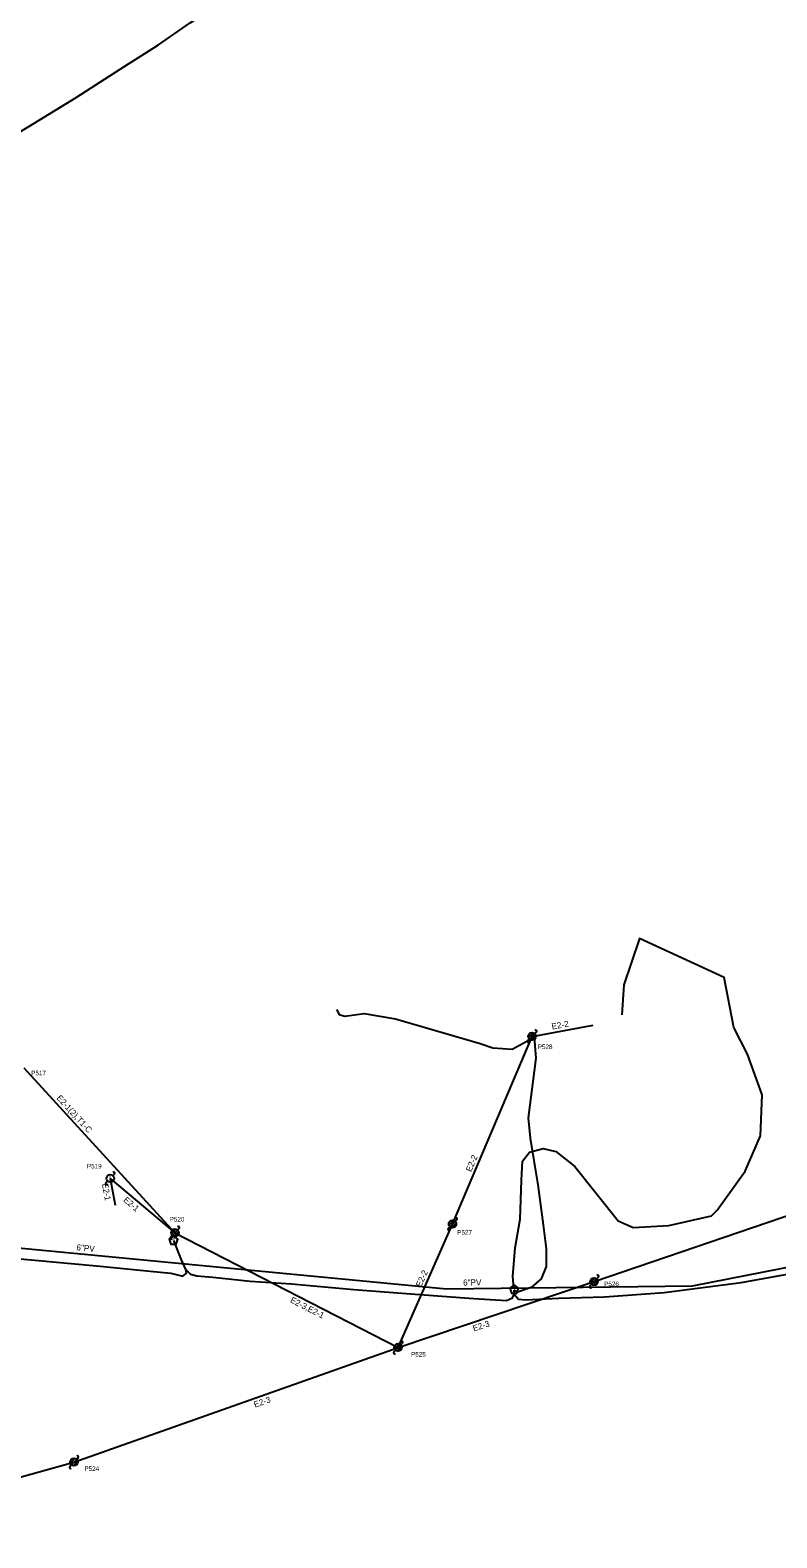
# Model space of a CAD drawing. Extents: x 1741604 to 1825760, y 1164229 to 1194908.
# Drawn here: x 1813275 to 1813765, y 1190349 to 1191338 of the extents above; entities that cross this region are included whole.
import ezdxf

# ---------------------------------------------------------------- set-up
doc = ezdxf.new("R2010")
doc.units = 0
for name, color, linetype in [('RD_EX_SU_Elec', 7, 'Continuous'), ('RD_EX_SU_H2O', 7, 'Continuous'), ('RD_EX_SU_Ovhd', 7, 'Continuous'), ('RD_EX_SU_Pole', 7, 'Continuous'), ('RD_EX_SU_Telecom', 7, 'Continuous'), ('RD_EX_SU_TX_H2O', 7, 'Continuous'), ('RD_EX_SU_TX_Pole', 7, 'Continuous')]:
    doc.layers.add(name, color=color, linetype=linetype)

# ---------------------------------------------------------------- blocks, each defined once
blk = doc.blocks.new('SUE_TPP')
at = {"layer": 'RD_EX_SU_Telecom'}
blk.add_lwpolyline([(0, 3), (-2.85, 0.93), (-1.76, -2.43), (1.76, -2.43), (2.85, 0.93)], close=True, dxfattribs=at)
blk.add_text('T', height=3.75, dxfattribs=at).set_placement((-1.25, -1.88))

msp = doc.modelspace()

# ---------------------------------------------------------------- linework, layer by layer
at = {"layer": 'RD_EX_SU_Elec'}
msp.add_lwpolyline([(1813074.17, 1191147.22), (1813079.49, 1191142.73), (1813083.35, 1191146.53), (1813090.24, 1191152.3), (1813113.65, 1191170.54), (1813131.4, 1191183.04), (1813147.43, 1191193.7), (1813174.94, 1191210.3), (1813193.18, 1191222.5), (1813212.55, 1191236.51), (1813242.91, 1191256.26), (1813274.11, 1191274.83), (1813305.14, 1191293.76), (1813336.93, 1191314.29), (1813359.03, 1191328.39), (1813379.8, 1191342.76), (1813412.74, 1191364.15), (1813434.94, 1191378.63), (1813468.04, 1191399.22), (1813497.48, 1191419.37)], dxfattribs=at)
at = {"layer": 'RD_EX_SU_H2O'}
msp.add_lwpolyline([(1813137.28, 1190560.13), (1813168.69, 1190548.44), (1813548.05, 1190512.01), (1813709.49, 1190513.95), (1813790.71, 1190529.92), (1813879.02, 1190555.32), (1814045.36, 1190620.16), (1814170.98, 1190673.34), (1814340.25, 1190745.39), (1814593.33, 1190851.84), (1815112.4, 1191071.44), (1815429.86, 1191203.06), (1815618.35, 1191283.39), (1815883.49, 1191395.05), (1816374.39, 1191600.1)], dxfattribs=at)
at = {"layer": 'RD_EX_SU_Ovhd'}
for p, q in [((1813604.22, 1190677.72), (1813644.26, 1190684.95)), ((1813552.01, 1190554.53), (1813604.22, 1190677.72)), ((1813270.85, 1190657.03), (1813369.89, 1190548.84)), ((1813644.92, 1190516.83), (1813856.8, 1190589.16)), ((1813327.48, 1190584.47), (1813369.89, 1190548.84)), ((1813327.48, 1190584.47), (1813330.66, 1190566.99)), ((1813369.89, 1190548.84), (1813516.3, 1190473.57)), ((1813516.3, 1190473.57), (1813552.01, 1190554.53)), ((1813516.3, 1190473.57), (1813644.92, 1190516.83)), ((1813303.67, 1190398.31), (1813516.3, 1190473.57)), ((1813113.89, 1190345.79), (1813303.67, 1190398.31))]:
    msp.add_line(p, q, dxfattribs=at)
at = {"layer": 'RD_EX_SU_Pole'}
for p, q in [((1813601.39, 1190674.89), (1813602.46, 1190675.95)), ((1813601.81, 1190677.07), (1813604.87, 1190680.13)), ((1813602.46, 1190675.95), (1813605.99, 1190679.49)), ((1813603.58, 1190675.3), (1813606.64, 1190678.36)), ((1813605.99, 1190679.49), (1813607.05, 1190680.55)), ((1813329.25, 1190586.23), (1813330.31, 1190587.29)), ((1813324.65, 1190581.64), (1813325.72, 1190582.7)), ((1813549.59, 1190553.89), (1813552.65, 1190556.95)), ((1813550.24, 1190552.76), (1813553.77, 1190556.3)), ((1813553.77, 1190556.3), (1813554.84, 1190557.36)), ((1813367.06, 1190546.01), (1813368.13, 1190547.07)), ((1813367.48, 1190548.19), (1813370.54, 1190551.25)), ((1813368.13, 1190547.07), (1813371.66, 1190550.61)), ((1813369.25, 1190546.42), (1813372.31, 1190549.49)), ((1813371.66, 1190550.61), (1813372.72, 1190551.67)), ((1813549.18, 1190551.7), (1813550.24, 1190552.76)), ((1813551.36, 1190552.12), (1813554.42, 1190555.18)), ((1813642.5, 1190516.19), (1813645.56, 1190519.25)), ((1813643.15, 1190515.07), (1813646.68, 1190518.6)), ((1813644.27, 1190514.42), (1813647.33, 1190517.48)), ((1813646.68, 1190518.6), (1813647.74, 1190519.66)), ((1813642.09, 1190514.01), (1813643.15, 1190515.07)), ((1813513.47, 1190470.74), (1813514.53, 1190471.8)), ((1813513.89, 1190472.92), (1813516.95, 1190475.99)), ((1813514.53, 1190471.8), (1813518.07, 1190475.34)), ((1813515.65, 1190471.16), (1813518.72, 1190474.22)), ((1813518.07, 1190475.34), (1813519.13, 1190476.4)), ((1813301.26, 1190397.67), (1813304.32, 1190400.73)), ((1813301.91, 1190396.54), (1813305.44, 1190400.08)), ((1813303.03, 1190395.9), (1813306.09, 1190398.96)), ((1813305.44, 1190400.08), (1813306.5, 1190401.14)), ((1813300.85, 1190395.48), (1813301.91, 1190396.54))]:
    msp.add_line(p, q, dxfattribs=at)
for centre in [(1813604.22, 1190677.72), (1813327.48, 1190584.47), (1813552.01, 1190554.53), (1813369.89, 1190548.84), (1813644.92, 1190516.83), (1813516.3, 1190473.57), (1813303.67, 1190398.31)]:
    msp.add_circle(centre, 2.5, dxfattribs=at)
for centre, start, end in [((1813601.92, 1190674.36), 135, 315), ((1813606.52, 1190681.08), 315, 135), ((1813329.78, 1190587.82), 315, 135), ((1813325.19, 1190581.11), 135, 315), ((1813554.3, 1190557.89), 315, 135), ((1813372.19, 1190552.2), 315, 135), ((1813549.71, 1190551.17), 135, 315), ((1813367.6, 1190545.48), 135, 315), ((1813647.21, 1190520.19), 315, 135), ((1813642.62, 1190513.48), 135, 315), ((1813518.6, 1190476.93), 315, 135), ((1813514, 1190470.21), 135, 315), ((1813305.97, 1190401.67), 315, 135), ((1813301.38, 1190394.95), 135, 315)]:
    msp.add_arc(centre, 0.75, start, end, dxfattribs=at)
at = {"layer": 'RD_EX_SU_Telecom'}
for points in [[(1813592.2, 1190512.27), (1813591.58, 1190520.2), (1813593.18, 1190538.89), (1813596.31, 1190557.84), (1813597.23, 1190583.39), (1813598.01, 1190595.83), (1813602.63, 1190601.72), (1813611.45, 1190604.04), (1813619.86, 1190602.19), (1813632.34, 1190592.39), (1813660.73, 1190556.55), (1813670.43, 1190552.36), (1813694.01, 1190553.55), (1813721.92, 1190559.95), (1813725.59, 1190563.57), (1813744.01, 1190589.22), (1813754.07, 1190612.54), (1813755.22, 1190639.35), (1813745.52, 1190665.97), (1813736.63, 1190683.45), (1813730.24, 1190716.26), (1813674.79, 1190741.98), (1813664.43, 1190711.59), (1813663.14, 1190691.81)], [(1813475.8, 1190695.38), (1813477.62, 1190691.96), (1813481.36, 1190690.96), (1813494, 1190692.66), (1813514.57, 1190689.18), (1813570.15, 1190673.12), (1813578.4, 1190670.16), (1813591.13, 1190669.29), (1813605.49, 1190677.21), (1813606.58, 1190663.31), (1813601.62, 1190624.21), (1813603.06, 1190610.93), (1813608.04, 1190580.18), (1813611.56, 1190554.08), (1813613.49, 1190538.25), (1813613.46, 1190526.59), (1813610.15, 1190518.68), (1813603.69, 1190512.91), (1813594.54, 1190509.9), (1813592.66, 1190511.16)], [(1813592.51, 1190508.63), (1813595.25, 1190505.28), (1813600.31, 1190504.81), (1813621.53, 1190505.89), (1813651.78, 1190506.69), (1813690.9, 1190509.66), (1813741.46, 1190516.19), (1813781.4, 1190523.39), (1813863.95, 1190545.47), (1813866.26, 1190551.47), (1813865.54, 1190556.28), (1813864.71, 1190557.84)], [(1813253.99, 1190533.12), (1813320.8, 1190526.93), (1813353.75, 1190523.6), (1813367.13, 1190522.28), (1813375.09, 1190520.41), (1813377.41, 1190522.28), (1813377.12, 1190524.81), (1813374.11, 1190530.98), (1813369.18, 1190543.74)], [(1813377.12, 1190524.81), (1813380.14, 1190521.61), (1813384.35, 1190520.53), (1813394.68, 1190519.71), (1813419.26, 1190517.09), (1813446.34, 1190515.21), (1813487.32, 1190511.57), (1813527.51, 1190508.49), (1813565.97, 1190505.66), (1813587.53, 1190504.42), (1813591.47, 1190506.03), (1813592.51, 1190508.63), (1813592.56, 1190511.19)]]:
    msp.add_lwpolyline(points, dxfattribs=at)

# ---------------------------------------------------------------- block references
for p in [(1813369.03, 1190543.78), (1813592.42, 1190511.55)]:
    msp.add_blockref('SUE_TPP', p, dxfattribs=at)

# ---------------------------------------------------------------- texts
at = {"layer": 'RD_EX_SU_Ovhd'}
for s, rotation, p in [('E2-2', 10.24048, (1813617.38, 1190682.13)), ('E2-1(2),T1-C', 312.47407, (1813291.9, 1190636.99)), ('E2-2', 67.02877, (1813564.21, 1190588.44)), ('E2-1', 280.29074, (1813322.04, 1190580.83)), ('E2-1', 319.96735, (1813335.7, 1190569.73)), ('E2-2', 66.201, (1813531.42, 1190512.82)), ('E2-3,E2-1', 332.79256, (1813445.17, 1190503.39)), ('E2-3', 18.59164, (1813566.07, 1190483.98)), ('E2-3', 19.49137, (1813422.46, 1190433.99))]:
    msp.add_text(s, height=4, rotation=rotation, dxfattribs=at).set_placement(p)
at = {"layer": 'RD_EX_SU_Pole'}
msp.add_text('L', height=4, dxfattribs=at).set_placement((1813326.62, 1190582.47))
at = {"layer": 'RD_EX_SU_TX_H2O'}
for rotation, p in [(354.51577, (1813305.11, 1190537.35)), (0.68711, (1813558.98, 1190514.14))]:
    msp.add_text('6"PV', height=4, rotation=rotation, dxfattribs=at).set_placement(p)
at = {"layer": 'RD_EX_SU_TX_Pole'}
for s, p in [('P528', (1813607.94, 1190669.37)), ('P517', (1813275.62, 1190652.17)), ('P519', (1813312.18, 1190591.02)), ('P520', (1813366.45, 1190556.19)), ('P527', (1813555.13, 1190547.56)), ('P526', (1813651.51, 1190513.75)), ('P525', (1813524.8, 1190467.52)), ('P524', (1813310.51, 1190392.54))]:
    msp.add_text(s, height=3, dxfattribs=at).set_placement(p)

doc.saveas('drawing.dxf')
